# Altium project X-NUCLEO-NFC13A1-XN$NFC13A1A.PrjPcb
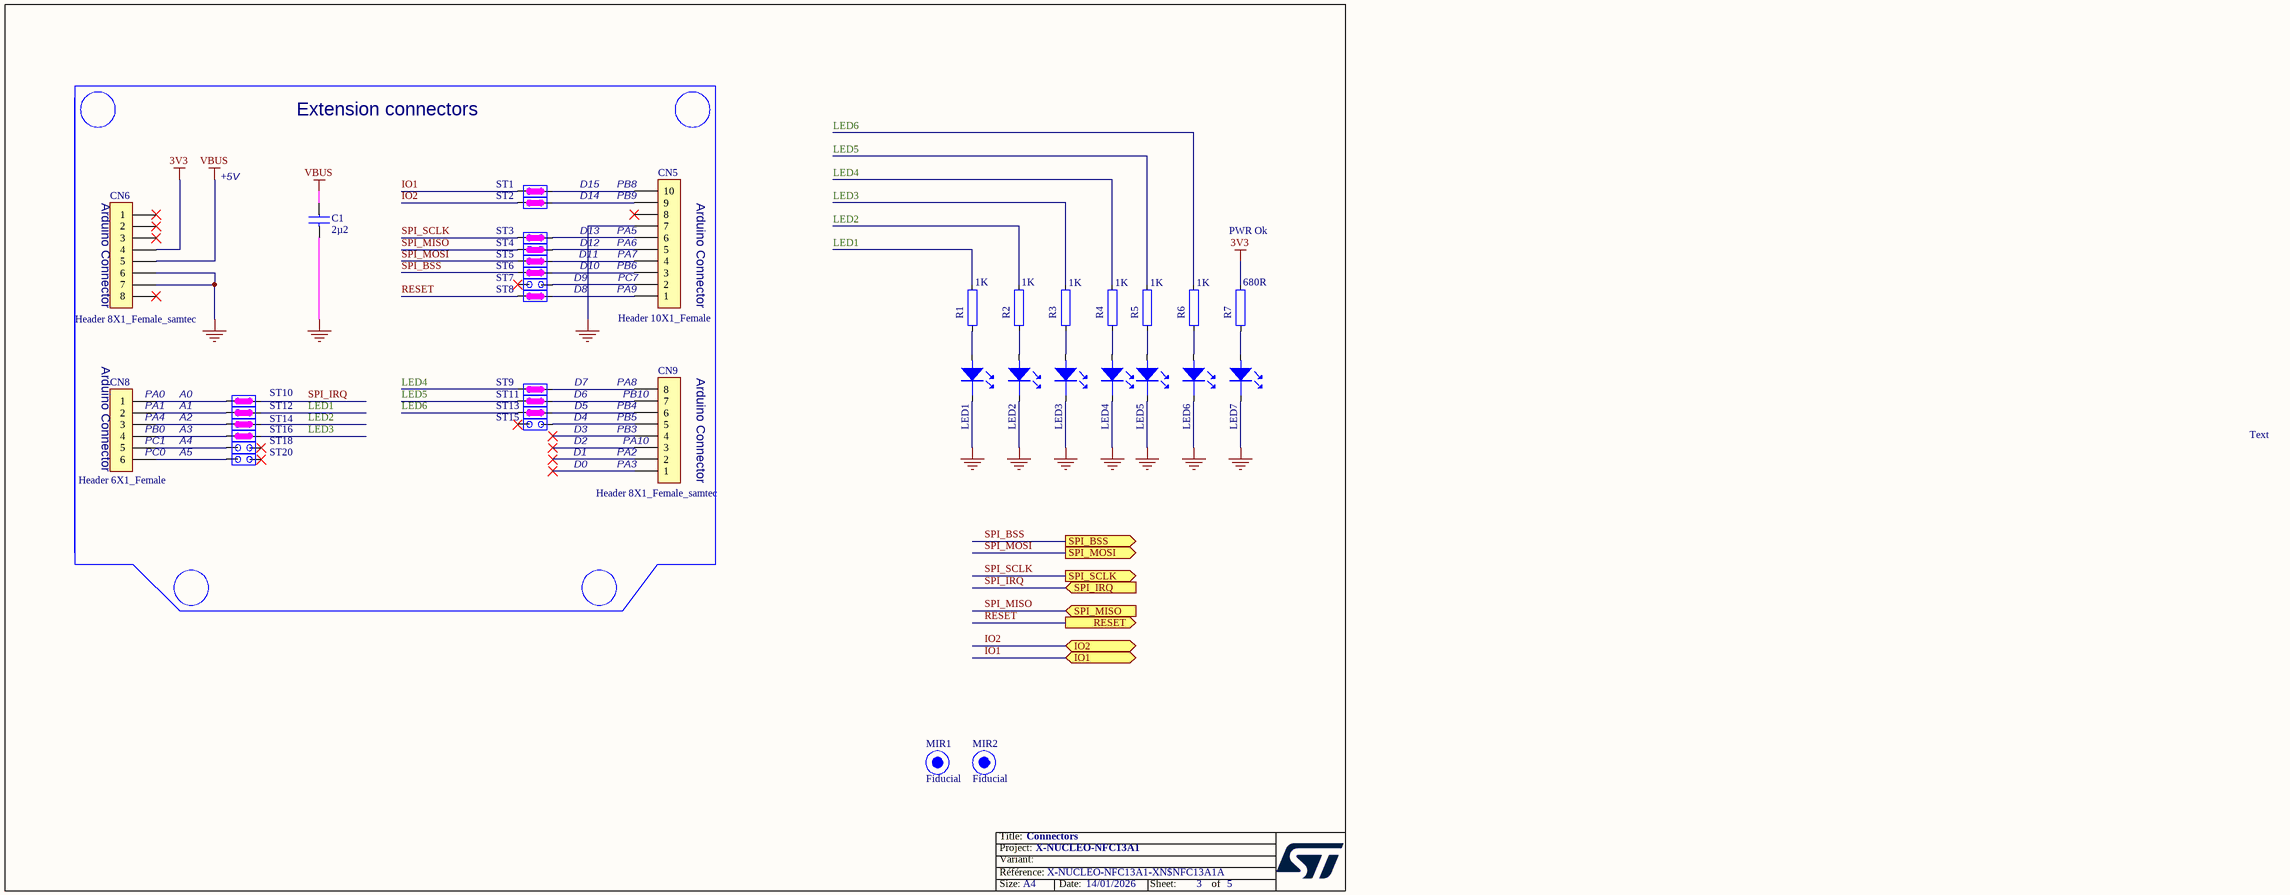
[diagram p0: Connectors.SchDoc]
Titre_BOM: X-NUCLEO-NFC13A1; text_ident_couches: X-NUCLEO-NFC13A1; Schematics_Title: X-NUCLEO-NFC13A1; Schematics_Revision: A; Company: ST MICROELECTRONICS; Board_Type: Expansion Board; Board_Revision: A; Board_Reference: X-NUCLEO-NFC13A1-XN$NFC13A1A; Board_PCB_Revision: A; Board_Finish_Good: XN$NFC13A1A; Board_Document_Date: 14/01/2026; Board_Commercial_Product: X-NUCLEO-NFC13A1; Board_Assembly_Revision: A
2 sheets, 89 parts. Net scope: flat (ports and power ports of the same name join across sheets).
Board file: X-NUCLEO-NFC13A1-XN$NFC13A1A.PcbDoc
Sheets:
  Connectors.SchDoc
  ST25R210.SchDoc

## Sheet Connectors.SchDoc: Connectors
size A4; PageSetup: Record=PageOptions¦CenterHorizontal=True¦CenterVertical=True¦PrintScale=0.73¦XCorrection=1.00¦YCorrection=1.00¦PrintKind=0¦BorderSize=5000000¦LeftOffset=0¦BottomOffset=0¦Orientation=2¦PaperLength=1000¦PaperWidth=1000¦Scale=100¦PaperSource=7¦PrintQuality=-3¦MediaType=1¦DitherType=10¦PrintScaleMode=1¦PaperKind=A4¦PaperIndex=9; Date: Not used; ApprovedBy: Not used; CheckedBy: Not used; Author: Not used; CompanyName: STMicroelectronics; DrawnBy: Not used; Engineer: Not used; Organization: Not used; Address1: Not used; Address2: Not used; Address3: Not used; Address4: Not used; DocumentNumber: 1; Revision: Not used; SheetNumber: 3; SheetTotal: 5

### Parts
C1  2µ2  [C0402]
CN5  Header 10X1_Female  [SAMTEC-SSQ-1x10-DROIT-STYLE-03]
CN6  Header 8X1_Female_samtec  [SAMTEC-SSQ-1x8-DROIT-STYLE-03]
CN8  Header 6X1_Female  [SAMTEC-SSQ-1x6-DROIT-STYLE-03]
CN9  Header 8X1_Female_samtec  [SAMTEC-SSQ-1x8-DROIT-STYLE-03]
LED1  (no value)  [D0603]
LED2  (no value)  [D0603]
LED3  (no value)  [D0603]
LED4  (no value)  [D0603]
LED5  (no value)  [D0603]
LED6  (no value)  [D0603]
LED7  (no value)  [D0603]
MIR1  Fiducial  [mire_optique_standard]  (no BOM)
MIR2  Fiducial  [mire_optique_standard]  (no BOM)
R1  1K  [R0402]
R2  1K  [R0402]
R3  1K  [R0402]
R4  1K  [R0402]
R5  1K  [R0402]
R6  1K  [R0402]
R7  680R  [R0402]
ST1  HE14 2PTS  [HE14-1x2-DROIT-AVEC-STRAP-CUIVRE-BOTTOM]  (value not drawn)  (net tie)
ST2  HE14 2PTS  [HE14-1x2-DROIT-AVEC-STRAP-CUIVRE-BOTTOM]  (value not drawn)  (net tie)
ST3  HE14 2PTS  [HE14-1x2-DROIT-AVEC-STRAP-CUIVRE-BOTTOM]  (value not drawn)  (net tie)
ST4  HE14 2PTS  [HE14-1x2-DROIT-AVEC-STRAP-CUIVRE-BOTTOM]  (value not drawn)  (net tie)
ST5  HE14 2PTS  [HE14-1x2-DROIT-AVEC-STRAP-CUIVRE-BOTTOM]  (value not drawn)  (net tie)
ST6  HE14 2PTS  [HE14-1x2-DROIT-AVEC-STRAP-CUIVRE-BOTTOM]  (value not drawn)  (net tie)
ST7  (no value)  [HE14-1x2-DROIT]
ST8  HE14 2PTS  [HE14-1x2-DROIT-AVEC-STRAP-CUIVRE-BOTTOM]  (value not drawn)  (net tie)
ST9  HE14 2PTS  [HE14-1x2-DROIT-AVEC-STRAP-CUIVRE-BOTTOM]  (value not drawn)  (net tie)
ST10  HE14 2PTS  [HE14-1x2-DROIT-AVEC-STRAP-CUIVRE-BOTTOM]  (value not drawn)  (net tie)
ST11  HE14 2PTS  [HE14-1x2-DROIT-AVEC-STRAP-CUIVRE-BOTTOM]  (value not drawn)  (net tie)
ST12  HE14 2PTS  [HE14-1x2-DROIT-AVEC-STRAP-CUIVRE-BOTTOM]  (value not drawn)  (net tie)
ST13  HE14 2PTS  [HE14-1x2-DROIT-AVEC-STRAP-CUIVRE-BOTTOM]  (value not drawn)  (net tie)
ST14  HE14 2PTS  [HE14-1x2-DROIT-AVEC-STRAP-CUIVRE-BOTTOM]  (value not drawn)  (net tie)
ST15  (no value)  [HE14-1x2-DROIT]
ST16  HE14 2PTS  [HE14-1x2-DROIT-AVEC-STRAP-CUIVRE-BOTTOM]  (value not drawn)  (net tie)
ST18  (no value)  [HE14-1x2-DROIT]
ST20  (no value)  [HE14-1x2-DROIT]

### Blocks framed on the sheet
Extension connectors: C1 CN5 CN6 CN8 CN9 ST1-ST16 ST18 ST20

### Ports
IO1 (bidir), IO2 (bidir), RESET (out), SPI_BSS (out), SPI_IRQ (in), SPI_MISO (in), SPI_MOSI (out), SPI_SCLK (out)

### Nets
3V3: CN6.4 R7.2
GND: C1.2 CN5.7 CN6.6 CN6.7 LED1.2 LED2.2 LED3.2 LED4.2 LED5.2 LED6.2 LED7.2
VBUS: C1.1 CN6.5
IO1: ST1.1 ; port IO1
IO2: ST2.1 ; port IO2
LED1: R1.2 ST12.2
LED2: R2.2 ST14.2
LED3: R3.2 ST16.2
LED4: R4.2 ST9.1
LED5: R5.2 ST11.1
LED6: R6.2 ST13.1
RESET: ST8.1 ; port RESET
SPI_BSS: ST6.1 ; port SPI_BSS
SPI_IRQ: ST10.2 ; port SPI_IRQ
SPI_MISO: ST4.1 ; port SPI_MISO
SPI_MOSI: ST5.1 ; port SPI_MOSI
SPI_SCLK: ST3.1 ; port SPI_SCLK
NetCN5_1: CN5.1 ST8.2
NetCN5_2: CN5.2 ST7.2
NetCN5_3: CN5.3 ST6.2
NetCN5_4: CN5.4 ST5.2
NetCN5_5: CN5.5 ST4.2
NetCN5_6: CN5.6 ST3.2
NetCN5_9: CN5.9 ST2.2
NetCN5_10: CN5.10 ST1.2
NetCN8_1: CN8.1 ST10.1
NetCN8_2: CN8.2 ST12.1
NetCN8_3: CN8.3 ST14.1
NetCN8_4: CN8.4 ST16.1
NetCN8_5: CN8.5 ST18.1
NetCN8_6: CN8.6 ST20.1
NetCN9_5: CN9.5 ST15.2
NetCN9_6: CN9.6 ST13.2
NetCN9_7: CN9.7 ST11.2
NetCN9_8: CN9.8 ST9.2
NetLED1_1: LED1.1 R1.1
NetLED2_1: LED2.1 R2.1
NetLED3_1: LED3.1 R3.1
NetLED4_1: LED4.1 R4.1
NetLED5_1: LED5.1 R5.1
NetLED6_1: LED6.1 R6.1
NetLED7_1: LED7.1 R7.1

Not connected (* = marked no-connect by the designer): CN5 8*; CN6 1* 2* 3* 8*; CN9 1* 2* 3* 4*; ST7 1*; ST15 1*; ST18 2*; ST20 2*

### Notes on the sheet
- (near CN6) Arduino Connector
- +5V
- D14
- D15
- PB9
- PB8
- (near CN5) Arduino Connector
- D11
- D13
- D12
- D10
- PA6
- PB6
- PA5
- PA7
- PWR Ok
- D9
- D8
- PA9
- PC7
- (near CN8) Arduino Connector
- D7
- PA8
- (near CN9) Arduino Connector
- (near CN8) PA0
- (near CN8) PA1
- (near CN8) PA4
- (near CN8) PB0
- (near CN8) PC1
- A0
- A1
- A2
- A3
- A4
- D4
- D3
- D2
- D6
- D5
- PB4
- PB3
- PB5
- (near CN9) PB10
- (near CN9) PA10
- Text
- (near CN8) PC0
- A5
- D1
- D0
- (near CN9) PA3
- PA2

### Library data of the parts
C1 = C_2µ2_0402_X5R: 2u2_X5R; Manufacturer: MURATA; Manufacturer Part Number: GRM155R60J225ME01D; 2nd Source: 0402, 2.2 µF, 6.3 V, ± 20%, X5R
CN5 = Header 10X1_Female_samtec: Header, 10-Pin, Single row,female; Manufacturer: Samtec; Manufacturer Part Number: SSQ-110-03-L-S; Comments: RECEPTACLE, 2.54MM, SINGLE ROW, 10WAY; 2nd source: doublesourcing allowed; PickPlace: No
CN6 CN9 = Header 8X1_Female_samtec: Header, 8-Pin, Single row,female; Manufacturer: Samtec; Manufacturer Part Number: SSQ-108-03-L-S; Comments: RECEPTACLE, 2.54MM, SINGLE ROW, 8WAY; 2nd source: doublesourcing allowed; PickPlace: No
CN8 = Header 6X1_Female: Header, 6-Pin, Single row,female; Manufacturer: Samtec; Manufacturer Part Number: SSQ-106-03-L-S; Comments: RECEPTACLE, 2.54MM, SINGLE ROW, 6 WAY; 2nd source: doublesourcing allowed; PickPlace: No
LED1-LED6 = LED-0603-Blue: Manufacturer: Lite-On; Manufacturer Part Number: LTST-C190TBKT; PickPlace: Yes
LED7 = LED-0603-Green: Manufacturer: Lite-On; Manufacturer Part Number: LTST-C190KGKT; PickPlace: Yes
MIR1 MIR2 = Mire-Optique: Fiducial for SMD Components; PickPlace: Yes
R1-R6 = R0402_1k: 1k, 0402; Manufacturer: Panasonic; Manufacturer Part Number: ERJ2GEJ102X; 2nd Source: 1 kohm, 50 V, 0402, >100 mW, ± 5%; PickPlace: Yes
R7 = R0402_680R: 680R, 0402; Manufacturer: Yageo; Manufacturer Part Number: RC0402JR-07680RL; 2nd Source: 680 Ohm ±5% 0.063W, 1/16W Chip Resistor 0402; PickPlace: Yes
ST1-ST6 ST8-ST14 ST16 = HE14-1X2-MALE-DROIT-NC-STRAP-CUIVRE-BOTTOM: CONN HE14 2PTS MALE VERTICAL NOT FITTED; 2nd Source: doublesourcing allowed
ST7 ST15 ST18 ST20 = HE14-1X2-MALE-DROIT-NC: CONN HE14 2PTS MALE VERTICAL NOT FITTED; 2nd Source: doublesourcing allowed; PickPlace: No

## Sheet ST25R210.SchDoc: ST25R210
size A4; PageSetup: Record=PageOptions¦CenterHorizontal=True¦CenterVertical=True¦PrintScale=0.97¦XCorrection=1.00¦YCorrection=1.00¦PrintKind=0¦BorderSize=5000000¦LeftOffset=0¦BottomOffset=0¦Orientation=2¦PaperLength=1000¦PaperWidth=1000¦Scale=100¦PaperSource=7¦PrintQuality=-4¦MediaType=1¦DitherType=10¦PaperKind=A4¦PrintScaleMode=1; Date: Not used; ApprovedBy: Not used; CheckedBy: Not used; Author: Not used; CompanyName: STMicroelectronics; DrawnBy: Not used; Engineer: Not used; Organization: Not used; Address1: Not used; Address2: Not used; Address3: Not used; Address4: Not used; DocumentNumber: 3; Revision: Not used; SheetNumber: 4; SheetTotal: 5
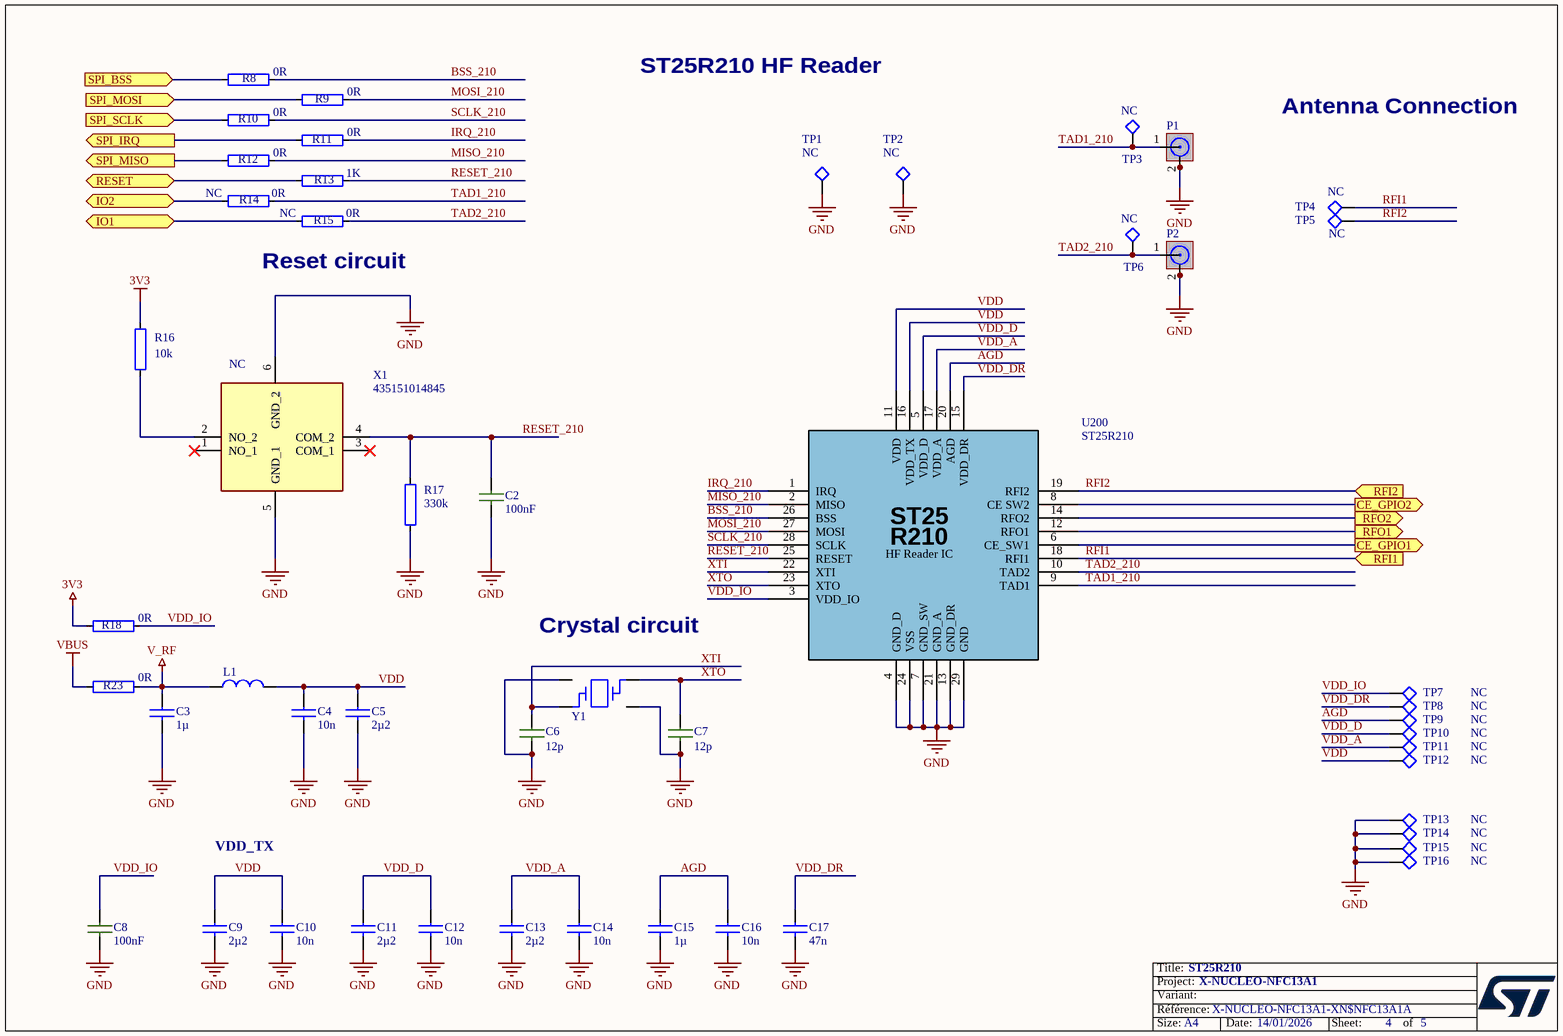
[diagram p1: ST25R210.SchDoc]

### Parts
C2  100nF  [C0402]
C3  1µ  [C0402]
C4  10n  [C0402]
C5  2µ2  [C0402]
C6  12p  [C0402]
C7  12p  [C0402]
C8  100nF  [C0402]
C9  2µ2  [C0402]
C10  10n  [C0402]
C11  2µ2  [C0402]
C12  10n  [C0402]
C13  2µ2  [C0402]
C14  10n  [C0402]
C15  1µ  [C0402]
C16  10n  [C0402]
C17  47n  [C0402]
L1  (no value)  [L0402]
P1  (no value)  [U FL Socket - HRS - Surface Mount]
P2  (no value)  [U FL Socket - HRS - Surface Mount]
R8  0R  [R0402]
R9  0R  [R0402]
R10  0R  [R0402]
R11  0R  [R0402]
R12  0R  [R0402]
R13  1K  [R0402]
R14  0R  [R0402]
R15  0R  [R0402]
R16  10k  [R0402]
R17  330k  [R0402]
R18  0R  [R0402]
R23  0R  [R0402]
TP1  NC  [1*1P_MALE]  (no BOM)
TP2  NC  [1*1P_MALE]  (no BOM)
TP3  NC  [1*1P_MALE]  (no BOM)
TP4  NC  [1*1P_MALE]  (no BOM)
TP5  NC  [1*1P_MALE]  (no BOM)
TP6  NC  [1*1P_MALE]  (no BOM)
TP7  NC  [1*1P_MALE round]  (no BOM)
TP8  NC  [1*1P_MALE round]  (no BOM)
TP9  NC  [1*1P_MALE round]  (no BOM)
TP10  NC  [1*1P_MALE round]  (no BOM)
TP11  NC  [1*1P_MALE round]  (no BOM)
TP12  NC  [1*1P_MALE round]  (no BOM)
TP13  NC  [1*1P_MALE round]  (no BOM)
TP14  NC  [1*1P_MALE round]  (no BOM)
TP15  NC  [1*1P_MALE round]  (no BOM)
TP16  NC  [1*1P_MALE round]  (no BOM)
U200  ST25R210  [ST25R210_QFN_28]
X1  435151014845  [435151014845]
Y1  ECS 27,12MHz Crystal  [XRCGB_F_MN]  (value not drawn)

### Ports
CE_GPIO1 (out), CE_GPIO2 (out), IO1 (bidir), IO2 (bidir), RESET (bidir), RFI1 (in), RFI2 (in), RFO1 (out), RFO2 (out), SPI_BSS (in), SPI_IRQ (out), SPI_MISO (out), SPI_MOSI (in), SPI_SCLK (in)

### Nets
3V3: R16.2 R18.2
GND: C2.2 C3.2 C4.2 C5.2 C6.2 C7.2 C8.2 C9.2 C10.2 C11.2 C12.2 C13.2 C14.2 C15.2 C16.2 C17.2 P1.2 P1.3 P2.2 P2.3 R17.1 TP1.1 TP2.1 TP13.1 TP14.1 TP15.1 TP16.1 U200.4(GND_D) U200.7(GND_SW) U200.13(GND_DR) U200.21(GND_A) U200.24(VSS) U200.29(GND) X1.5(GND_1) X1.6(GND_2) Y1.2 Y1.4
V_RF: C3.1 L1.2 R23.1
VBUS: R23.2
AGD: C15.1 C16.1 TP9.1 U200.20(AGD)
BSS_210: R8.1 U200.26(BSS)
CE_GPIO1: U200.6(CE_SW1) ; port CE_GPIO1
CE_GPIO2: U200.8(CE_SW2) ; port CE_GPIO2
IO1: R15.2 ; port IO1
IO2: R14.2 ; port IO2
IRQ_210: R11.1 U200.1(IRQ)
MISO_210: R12.1 U200.2(MISO)
MOSI_210: R9.1 U200.27(MOSI)
RESET: R13.2 ; port RESET
RESET_210: C2.1 R13.1 R17.2 U200.25(RESET) X1.4(COM_2)
RFI1: TP4.1 U200.18(RFI1) ; port RFI1
RFI2: TP5.1 U200.19(RFI2) ; port RFI2
RFO1: U200.12(RFO1) ; port RFO1
RFO2: U200.14(RFO2) ; port RFO2
SCLK_210: R10.1 U200.28(SCLK)
SPI_BSS: R8.2 ; port SPI_BSS
SPI_IRQ: R11.2 ; port SPI_IRQ
SPI_MISO: R12.2 ; port SPI_MISO
SPI_MOSI: R9.2 ; port SPI_MOSI
SPI_SCLK: R10.2 ; port SPI_SCLK
TAD1_210: P1.1 R14.1 TP3.1 U200.9(TAD1)
TAD2_210: P2.1 R15.1 TP6.1 U200.10(TAD2)
VDD: C4.1 C5.1 C9.1 C10.1 L1.1 TP12.1 U200.11(VDD) U200.16(VDD_TX)
VDD_A: C13.1 C14.1 TP11.1 U200.17(VDD_A)
VDD_D: C11.1 C12.1 TP10.1 U200.5(VDD_D)
VDD_DR: C17.1 TP8.1 U200.15(VDD_DR)
VDD_IO: C8.1 R18.1 TP7.1 U200.3(VDD_IO)
XTI: C6.1 U200.22(XTI) Y1.3
XTO: C7.1 U200.23(XTO) Y1.1
NetR16_1: R16.1 X1.2(NO_2)

Not connected (* = marked no-connect by the designer): X1 1(NO_1)* 3(COM_1)*

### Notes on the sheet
- ST25R210 HF Reader
- Antenna Connection
- (near R15) Reset circuit
- (near Y1) Crystal circuit
- VDD_TX

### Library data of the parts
C2 C8 = C_100nF_0402_AEC-Q: 100n_X7s; Manufacturer: Murata; Manufacturer Part Number: GCM155R71H104KE02J; 2nd Source: AEC-Q200 100nF ±10% 50V 0402
C3 C15 = C_1µ_0402_X5R: 1u_X5R; Manufacturer: MURATA; Manufacturer Part Number: GRM155R61C105KA12D; 2nd Source: 0402, 1 µF, 16 V, ± 10%, X5R,
C4 C10 C12 C14 C16 = C_10n_0402_X7R: 10n_x7R; Manufacturer: AVX; Manufacturer Part Number: 04023C103KAT2A; 2nd Source: 0402, 0.01 µF, 25 V, ± 10%, X7R
C5 C9 C11 C13 = C_2µ2_0402_X5R: as C1 on sheet Connectors
C6 C7 = C_12p_0402_AEC-Q: 12p_COG; Manufacturer: Murta; Manufacturer Part Number: GCM1555C1H120FA16D; 2nd Source: AEC-Q200 12pF ±1% 100V  C0G 0402
C17 = C_47nF_0402_AEC-Q: 47n_X7s; Manufacturer: Murata; Manufacturer Part Number: GCM155R71E473KA55D; 2nd Source: AEC-Q200 47nF ±10% 10V 0402
L1 = FB_0402: Manufacturer: muRata; Manufacturer Part Number: BLM15EG121SH1D; 2nd Source: No
P1 P2 = U.FL-R-SMT-1: Manufacturer: HIROSE(HRS); Manufacturer Part Number: U.FL-R-SMT-1(10); 2nd Source: yes
R8-R12 R14 R15 R18 R23 = R0402_0R: 0R, 0402; Manufacturer: VISHAY; Manufacturer Part Number: CRCW04020000ZSTD; 2nd Source: 0 ohm, 50 V, 0402, >62.5 mW
R13 = R0402_1k: as R1 on sheet Connectors
R16 = R0402_10k: 10k, 0402; Manufacturer: MULTICOMP; Manufacturer Part Number: MC00625W0402110K; 2nd Source: 10 kohm, 50 V, 0402, >62.5 mW, ± 1%
R17 = R0402_330k: 330k, 0402; Manufacturer: VISHAY; Manufacturer Part Number: CRCW0402330KFKED; 2nd Source: 330 kohm, 50 V, 0402, >62.5 mW, ± 1%
TP1-TP6 = Test point 0.5mm_1
TP7-TP10 TP12-TP16 = Test point 0.5mm: Value: d.n.p.
TP11 = Test point 0.5mm
U200 = ST25R210_QFN28: HF Reader IC QFN28; Manufacturer: STMicroelectronics
X1 = 435151014845: Tactile Switches WS-TASV Tact Switch; Manufacturer: Wurth Elektronik; Geometry.Height: 1.4mm
Y1 = ECS-271.2-10-37: CRYSTAL 27.1200MHZ 10PF SMD; Manufacturer Part Number: ECS-271.2-10-37-CKM-TR

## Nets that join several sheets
3V3: Connectors (CN6.4 R7.2), ST25R210 (R16.2 R18.2)
GND: Connectors (11 pins), ST25R210 (37 pins)
VBUS: Connectors (C1.1 CN6.5), ST25R210 (R23.2)
IO1: Connectors (ST1.1), ST25R210 (R15.2)
IO2: Connectors (ST2.1), ST25R210 (R14.2)
RESET: Connectors (ST8.1), ST25R210 (R13.2)
SPI_BSS: Connectors (ST6.1), ST25R210 (R8.2)
SPI_IRQ: Connectors (ST10.2), ST25R210 (R11.2)
SPI_MISO: Connectors (ST4.1), ST25R210 (R12.2)
SPI_MOSI: Connectors (ST5.1), ST25R210 (R9.2)
SPI_SCLK: Connectors (ST3.1), ST25R210 (R10.2)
